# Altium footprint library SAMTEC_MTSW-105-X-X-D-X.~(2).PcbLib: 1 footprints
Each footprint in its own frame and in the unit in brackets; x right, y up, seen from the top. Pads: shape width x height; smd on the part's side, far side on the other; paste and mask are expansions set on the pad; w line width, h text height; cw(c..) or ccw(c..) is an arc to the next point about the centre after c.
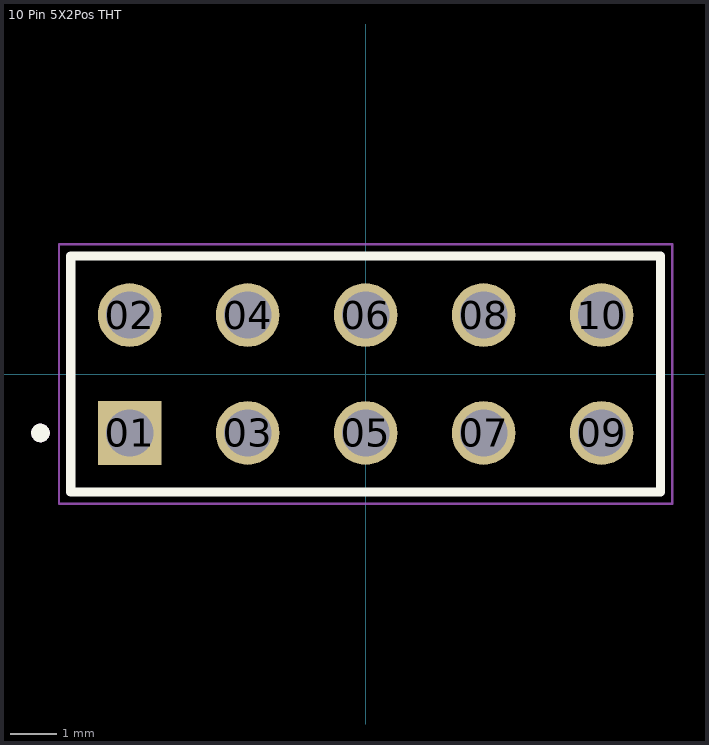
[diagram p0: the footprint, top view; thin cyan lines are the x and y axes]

## 10 Pin 5X2Pos THT [mm] "10 Pin 5X2Pos THT BergeStick 2.54MM MTSW-105-X-X-D-X"
pads (10):
  rect 1.37x1.37 / inner round 1.37 / far side rect 1.37x1.37 hole 1.02: 01(-5.08,-1.27)
  round 1.37 hole 1.02: 02(-5.08,1.27) 03(-2.54,-1.27) 04(-2.54,1.27) 05(0,-1.27) 06(0,1.27) 07(2.54,-1.27) 08(2.54,1.27) 09(5.08,-1.27) 10(5.08,1.27)
Top Overlay:
  circle w0.2: c-7,-1.27 r0.1
  lines w0.2: -6.35,-2.54 6.35,-2.54 6.35,2.54 -6.35,2.54 -6.35,-2.54
Mechanical 13:
  circle w0.2: c-7,-1.27 r0.1
  lines w0.1: -6.35,-2.54 -6.35,2.54 6.35,2.54 6.35,-2.54 -6.35,-2.54
Mechanical 15:
  lines w0.05: -6.6,-2.79 6.6,-2.79 6.6,2.79 -6.6,2.79 -6.6,-2.79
